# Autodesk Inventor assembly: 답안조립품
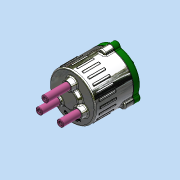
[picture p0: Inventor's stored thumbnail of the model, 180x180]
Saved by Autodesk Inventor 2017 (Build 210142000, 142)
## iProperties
Part Number: 답안조립품
Material: 일반
Document SubType Name: Assembly
Designer: MRC
Author: MRC
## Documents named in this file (15)
- C:\Users\MRC\Desktop\620811V1004\답안조립품.iam
- C:\Users\MRC\Desktop\620811V1004\본체.ipt
- C:\Users\MRC\Desktop\620811V1004\가변스프링1.ipt
- C:\Users\MRC\Desktop\620811V1004\가변스프링2.ipt
- C:\Users\MRC\Desktop\620811V1004\가변스프링3.ipt
- C:\Users\MRC\Desktop\620811V1004\개스킷.ipt
- C:\Users\MRC\Desktop\620811V1004\멈춤링 10x1.ipt
- C:\Users\MRC\Desktop\620811V1004\멈춤링 22x1.2.ipt
- C:\Users\MRC\Desktop\620811V1004\메인 축.ipt
- C:\Users\MRC\Desktop\620811V1004\베어링 NA 4900.ipt
- C:\Users\MRC\Desktop\620811V1004\볼트 M5.ipt
- C:\Users\MRC\Desktop\620811V1004\슬라이드 축.ipt
- C:\Users\MRC\Desktop\620811V1004\오일 실.ipt
- C:\Users\MRC\Desktop\620811V1004\커버.ipt
- C:\Users\MRC\Desktop\620811V1004\판캠.ipt
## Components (4 placed, 4 different names)
1. 가변스프링1:1
2. 가변스프링2:1
3. 가변스프링3:1
4. 개스킷:1
